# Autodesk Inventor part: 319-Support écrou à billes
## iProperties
Author: Philippe
Created: 2001-12
Part Number: 319-Support écrou à billes
Material: Par défaut
Document SubType Name: Modélisation
Designer: Philippe
Control State: 0
Master: False
Checked Out: False
PropertySet Name: Design Tracking Control
Shininess: 64.0
Angle Display Precision: 2
Document Length Units: 11269
Document Angle Units: 11283
Document Time Units: 11279
Document Mass Units: 11290
Document Length Units Precision: 3
Document Angle Units Precision: 2
Compacted: False
PropertySet Name: _Private Model Information
Density: 0.0
Volumn: 0.0
Area: 0.0
PropertySet Name: Model Information
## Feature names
1. Extrusion1
